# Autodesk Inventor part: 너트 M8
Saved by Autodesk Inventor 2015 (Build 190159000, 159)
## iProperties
Created: 2025-08
Part Number: 너트 M8
Material: 일반
Document SubType Name: Modeling
Designer: user
Density: 1 g/cm^3
Appearance: 기본값
Author: user
Author: jhkim
Description: 플랜지붙이 6각 너트 - 일반 스레드
Creation Date: 2025-08-05
Sending System: Autodesk Inventor 2026
Preprocessor: ST-DEVELOPER v20.1
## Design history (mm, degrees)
node "너트 M81"
body "Solid1"
node "기준1"
